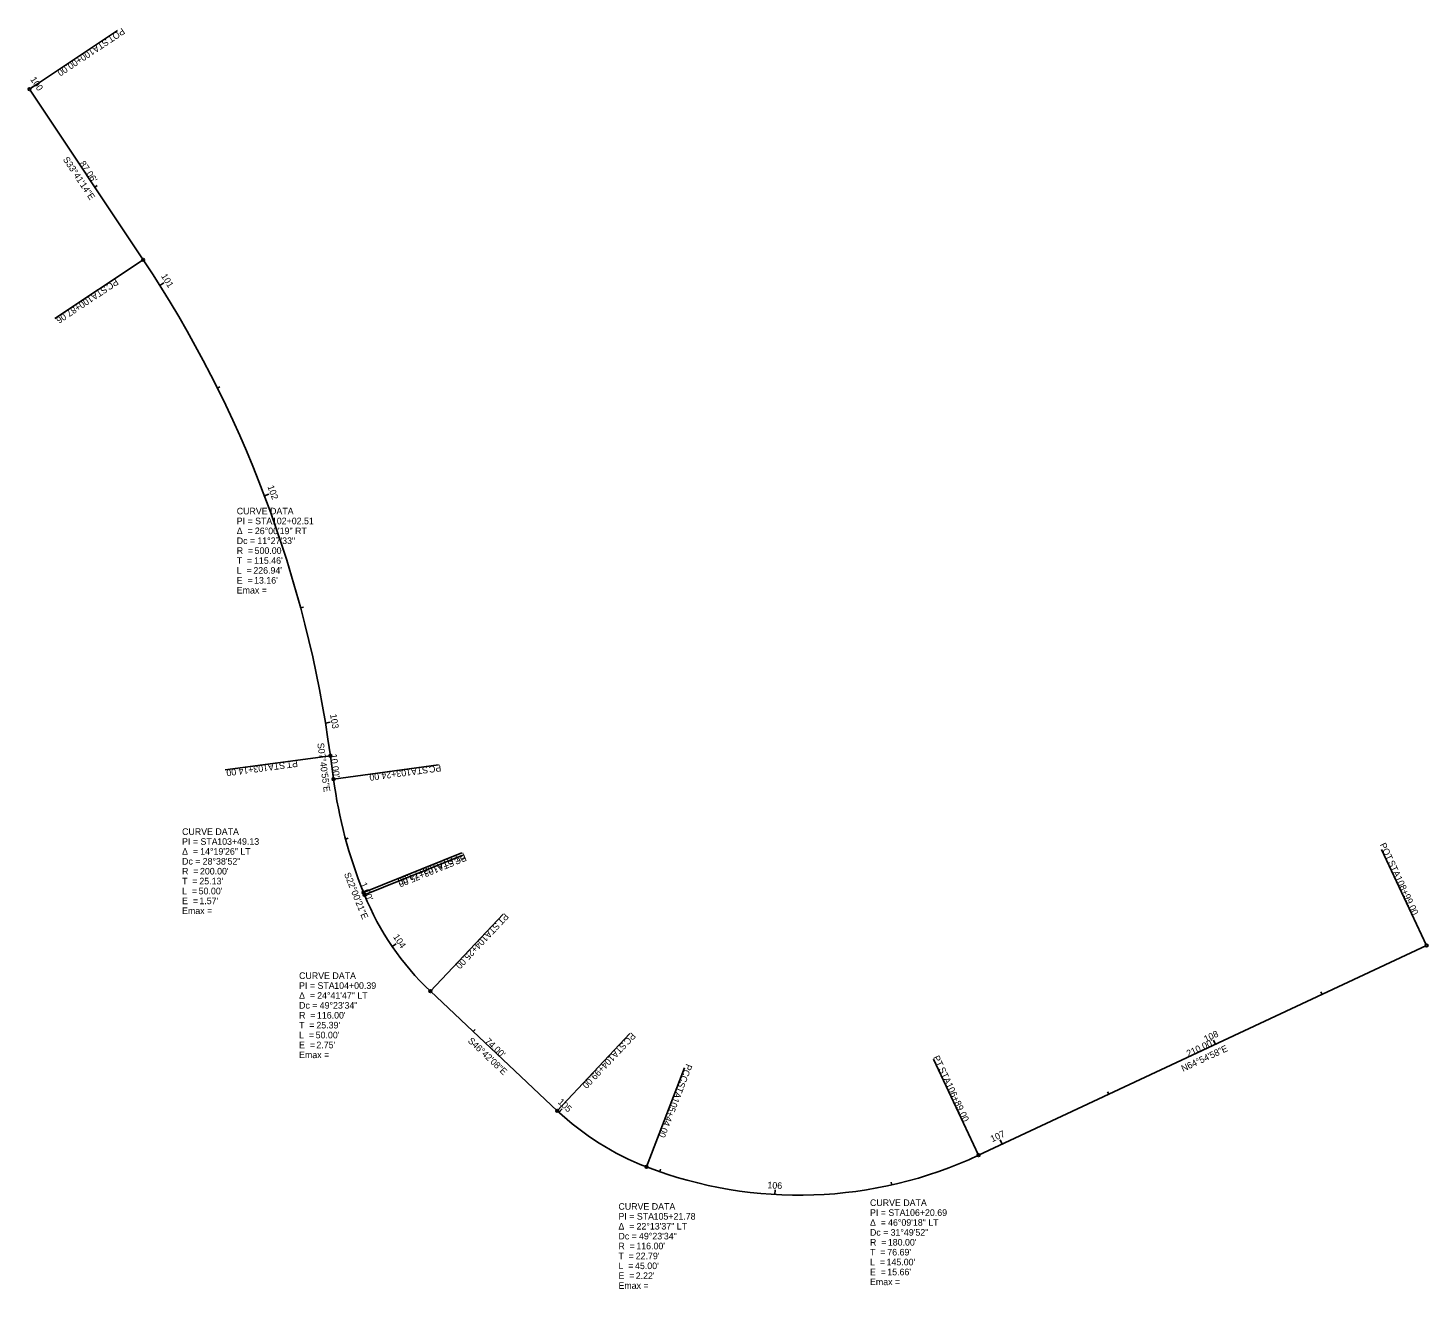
# Model space of a CAD drawing. Extents: x 1865318 to 1865913, y 743981 to 744516.
import ezdxf

# ---------------------------------------------------------------- set-up
doc = ezdxf.new("R2010")
doc.units = 0
for name, color, linetype in [('_CIVIL_CONSTRUCTION', 7, 'Continuous'), ('Default', 7, 'Continuous'), ('GT_Project_Soil_Boring', 7, 'Continuous'), ('PF_P_Text_Curve', 7, 'Continuous'), ('SH_Major_Grid_Line', 7, 'Continuous'), ('SH_Masking', 7, 'Continuous'), ('SH_Text', 7, 'Continuous')]:
    doc.layers.add(name, color=color, linetype=linetype)

msp = doc.modelspace()

# ---------------------------------------------------------------- linework, layer by layer
at = {"layer": 'Default'}
msp.add_line((1865721.96, 744037.44), (1865912.16, 744126.46), dxfattribs=at)
at = {"layer": 'GT_Project_Soil_Boring'}
for p, q in [((1865367.27, 744417.56), (1865318.99, 744490)), ((1865318.99, 744490), (1865367.27, 744417.56)), ((1865318.99, 744490), (1865367.27, 744417.56)), ((1865448.08, 744197.15), (1865446.75, 744207.06)), ((1865446.75, 744207.06), (1865448.08, 744197.15)), ((1865446.75, 744207.06), (1865448.08, 744197.15)), ((1865461.24, 744148.02), (1865460.86, 744148.95)), ((1865460.86, 744148.95), (1865461.24, 744148.02)), ((1865460.86, 744148.95), (1865461.24, 744148.02)), ((1865721.96, 744037.44), (1865912.16, 744126.46)), ((1865489.23, 744107.06), (1865543.09, 744056.31)), ((1865489.23, 744107.06), (1865543.09, 744056.31))]:
    msp.add_line(p, q, dxfattribs=at)
for centre, radius, start, end in [((1864951.23, 744140.23), 500, 7.68182, 33.68723), ((1864951.23, 744140.23), 500, 7.68182, 33.68723), ((1864951.23, 744140.23), 500, 7.68182, 33.68723), ((1865646.29, 744223.89), 200, 187.68182, 202.00577), ((1865646.29, 744223.89), 200, 187.68182, 202.00577), ((1865646.29, 744223.89), 200, 187.68182, 202.00577), ((1865568.78, 744191.49), 116, 202.00577, 226.70222), ((1865568.78, 744191.49), 116, 202.00577, 226.70222), ((1865568.78, 744191.49), 116, 202.00577, 226.70222), ((1865622.64, 744140.74), 116, 226.70222, 248.92903), ((1865622.64, 744140.74), 116, 226.70222, 248.92903), ((1865622.64, 744140.74), 116, 226.70222, 248.92903), ((1865645.65, 744200.46), 180, 248.92903, 295.08397), ((1865645.65, 744200.46), 180, 248.92903, 295.08397), ((1865645.65, 744200.46), 180, 248.92903, 295.08397)]:
    msp.add_arc(centre, radius, start, end, dxfattribs=at)
at = {"layer": 'SH_Major_Grid_Line'}
for p, q in [((1865318.99, 744490), (1865320.65, 744491.11)), ((1865346.72, 744448.39), (1865347.72, 744449.06)), ((1865374.31, 744406.7), (1865376.01, 744407.76)), ((1865398.8, 744363.13), (1865399.88, 744363.66)), ((1865418.82, 744317.33), (1865420.69, 744318.04)), ((1865434.16, 744269.77), (1865435.32, 744270.08)), ((1865444.68, 744220.91), (1865446.66, 744221.23)), ((1865453.22, 744171.68), (1865454.38, 744172)), ((1865473.02, 744126.02), (1865474.67, 744127.15)), ((1865867.78, 744105.69), (1865867.27, 744106.78)), ((1865507.43, 744089.91), (1865508.25, 744090.79)), ((1865822.5, 744084.5), (1865821.65, 744086.31)), ((1865777.21, 744063.3), (1865776.7, 744064.38)), ((1865543.82, 744055.63), (1865545.18, 744057.1)), ((1865731.93, 744042.1), (1865731.08, 744043.91)), ((1865586.57, 744030.43), (1865586.97, 744031.56)), ((1865685.13, 744024.84), (1865684.87, 744026.01)), ((1865635.46, 744020.75), (1865635.58, 744022.74))]:
    msp.add_line(p, q, dxfattribs=at)
at = {"layer": 'SH_Text'}
for p, q in [((1865318.99, 744490), (1865356.43, 744514.96)), ((1865367.27, 744417.56), (1865329.83, 744392.6)), ((1865446.75, 744207.06), (1865402.15, 744201.05)), ((1865448.08, 744197.15), (1865492.68, 744203.17)), ((1865912.16, 744126.46), (1865893.08, 744167.22)), ((1865460.86, 744148.95), (1865502.58, 744165.81)), ((1865461.24, 744148.02), (1865502.96, 744164.88)), ((1865489.23, 744107.06), (1865520.09, 744139.81)), ((1865543.09, 744056.31), (1865573.95, 744089.06)), ((1865721.96, 744037.44), (1865702.88, 744078.19)), ((1865580.94, 744032.49), (1865597.11, 744074.49))]:
    msp.add_line(p, q, dxfattribs=at)
for centre in [(1865318.99, 744490), (1865367.27, 744417.56), (1865446.75, 744207.06), (1865448.08, 744197.15), (1865460.86, 744148.95), (1865461.24, 744148.02), (1865912.16, 744126.46), (1865489.23, 744107.06), (1865543.09, 744056.31), (1865721.96, 744037.44), (1865580.94, 744032.49)]:
    msp.add_circle(centre, 0.6, dxfattribs=at)

# ---------------------------------------------------------------- texts
at = {"layer": '_CIVIL_CONSTRUCTION'}
for s, rotation, p in [("87.06'", 303.68723, (1865340.08, 744458.43)), ("10.00'", 277.68182, (1865446.71, 744207.63)), ("1.00'", 292.00577, (1865459.42, 744152.62)), ("74.00'", 316.70222, (1865512.14, 744085.53)), ("210.00'", 25.08397, (1865810.99, 744079.16))]:
    msp.add_text(s, height=2.8, rotation=rotation, dxfattribs=at).set_placement(p)
at = {"layer": 'PF_P_Text_Curve'}
for s, p in [('CURVE DATA', (1865407.01, 744309.51)), ('Δ  = ', (1865407.01, 744301.11)), ('PI = STA ', (1865407.01, 744305.31)), ('26°00\'19" RT', (1865414.69, 744301.11)), ('102+02.51', (1865421.93, 744305.31)), ('Dc = ', (1865407.01, 744296.91)), ('11°27\'33"', (1865415.75, 744296.91)), ('R  = ', (1865407.01, 744292.71)), ("115.46'", (1865414.35, 744288.51)), ("500.00'", (1865414.59, 744292.71)), ('T  = ', (1865407.01, 744288.51)), ('L  = ', (1865407.01, 744284.31)), ("226.94'", (1865414.05, 744284.31)), ('E  = ', (1865407.01, 744280.11)), ("13.16'", (1865414.35, 744280.11)), ('Emax = ', (1865407.01, 744275.91)), ('CURVE DATA', (1865383.8, 744173.42)), ('Δ  = ', (1865383.8, 744165.02)), ('PI = STA ', (1865383.8, 744169.22)), ('14°19\'26" LT', (1865391.48, 744165.02)), ('103+49.13', (1865398.73, 744169.22)), ('Dc = ', (1865383.8, 744160.82)), ('28°38\'52"', (1865392.54, 744160.82)), ('T  = ', (1865383.8, 744152.42)), ('R  = ', (1865383.8, 744156.62)), ("25.13'", (1865391.14, 744152.42)), ("200.00'", (1865391.39, 744156.62)), ('L  = ', (1865383.8, 744148.22)), ("50.00'", (1865390.85, 744148.22)), ('E  = ', (1865383.8, 744144.02)), ("1.57'", (1865391.15, 744144.02)), ('Emax = ', (1865383.8, 744139.82)), ('CURVE DATA', (1865433.48, 744112.26)), ('PI = STA ', (1865433.48, 744108.06)), ('104+00.39', (1865448.4, 744108.06)), ('Δ  = ', (1865433.48, 744103.86)), ('Dc = ', (1865433.48, 744099.66)), ('24°41\'47" LT', (1865441.15, 744103.86)), ('49°23\'34"', (1865442.22, 744099.66)), ('R  = ', (1865433.48, 744095.46)), ("116.00'", (1865441.06, 744095.46)), ('T  = ', (1865433.48, 744091.26)), ('L  = ', (1865433.48, 744087.06)), ("50.00'", (1865440.52, 744087.06)), ("25.39'", (1865440.82, 744091.26)), ('E  = ', (1865433.48, 744082.86)), ("2.75'", (1865440.82, 744082.86)), ('Emax = ', (1865433.48, 744078.66)), ('CURVE DATA', (1865675.85, 744015.88)), ('CURVE DATA', (1865569.06, 744014.29)), ('PI = STA ', (1865569.06, 744010.09)), ('105+21.78', (1865583.99, 744010.09)), ('PI = STA ', (1865675.85, 744011.68)), ('106+20.69', (1865690.77, 744011.68)), ('Δ  = ', (1865569.06, 744005.89)), ('22°13\'37" LT', (1865576.74, 744005.89)), ('Δ  = ', (1865675.85, 744007.48)), ('Dc = ', (1865675.85, 744003.28)), ('46°09\'18" LT', (1865683.53, 744007.48)), ('31°49\'52"', (1865684.59, 744003.28)), ('Dc = ', (1865569.06, 744001.69)), ('R  = ', (1865569.06, 743997.49)), ("116.00'", (1865576.65, 743997.49)), ('49°23\'34"', (1865577.8, 744001.69)), ('R  = ', (1865675.85, 743999.08)), ("180.00'", (1865683.43, 743999.08)), ('T  = ', (1865569.06, 743993.29)), ("22.79'", (1865576.4, 743993.29)), ('T  = ', (1865675.85, 743994.88)), ("76.69'", (1865683.19, 743994.88)), ('L  = ', (1865569.06, 743989.09)), ("45.00'", (1865576.1, 743989.09)), ('L  = ', (1865675.85, 743990.68)), ('E  = ', (1865675.85, 743986.48)), ("145.00'", (1865682.89, 743990.68)), ("15.66'", (1865683.19, 743986.48)), ('E  = ', (1865569.06, 743984.89)), ('Emax = ', (1865569.06, 743980.69)), ("2.22'", (1865576.4, 743984.89)), ('Emax = ', (1865675.85, 743982.28))]:
    msp.add_text(s, height=2.8, dxfattribs=at).set_placement(p)
at = {"layer": 'SH_Major_Grid_Line'}
for s, rotation, p in [('100', 303.68723, (1865319.21, 744494.17)), ('101', 302.20396, (1865374.75, 744410.69)), ('102', 290.7448, (1865419.99, 744321.28)), ('103', 279.28564, (1865446.62, 744224.54)), ('104', 304.35597, (1865473.24, 744130.14)), ('108', 25.08397, (1865818.42, 744085.35)), ('105', 317.19813, (1865543.1, 744059.71)), ('107', 25.08397, (1865727.77, 744042.92)), ('106', 356.75566, (1865632.25, 744023.43))]:
    msp.add_text(s, height=2.8, rotation=rotation, dxfattribs=at).set_placement(p)
at = {"layer": 'SH_Masking'}
for s, rotation, p in [('S33°41\'14"E', 303.68723, (1865333.07, 744460.22)), ('S07°40\'55"E', 277.68182, (1865441.2, 744212.31)), ('S22°00\'21"E', 292.00577, (1865452.5, 744156.83)), ('S46°42\'08"E', 316.70222, (1865504.91, 744085.7)), ('N64°54\'58"E', 25.08397, (1865808.8, 744072.79))]:
    msp.add_text(s, height=2.8, rotation=rotation, dxfattribs=at).set_placement(p)
at = {"layer": 'SH_Text'}
for s, rotation, p in [(' STA ', 213.68723, (1865352.33, 744512.17)), ('POT', 213.68723, (1865358.32, 744516.16)), ('100+00.00', 213.68723, (1865345.39, 744507.55)), (' STA ', 213.68723, (1865351.79, 744407.18)), ('PC', 213.68723, (1865355.6, 744409.73)), ('100+87.06', 213.68723, (1865344.85, 744402.56)), ('103+14.00', 187.68182, (1865420.09, 744203.43)), (' STA ', 187.68182, (1865428.35, 744204.54)), ('PT', 187.68182, (1865432.73, 744205.13)), (' STA ', 187.68182, (1865489.07, 744202.64)), ('PC', 187.68182, (1865493.61, 744203.25)), ('103+24.00', 187.68182, (1865480.81, 744201.53)), ('POT', 295.08397, (1865892.17, 744169.27)), ('103+74.00', 202.00577, (1865491.56, 744161.31)), (' STA ', 202.00577, (1865499.29, 744164.44)), (' STA ', 202.00577, (1865499.59, 744163.48)), ('PC', 202.00577, (1865503.84, 744165.19)), ('PT', 202.00577, (1865503.38, 744166.09)), (' STA ', 295.08397, (1865895.22, 744162.75)), ('103+75.00', 202.00577, (1865491.86, 744160.35)), ('108+99.00', 295.08397, (1865898.75, 744155.2)), ('PT', 226.70222, (1865520.71, 744140.4)), ('104+25.00', 226.70222, (1865511.96, 744131.12)), (' STA ', 226.70222, (1865517.68, 744137.19)), ('PC', 226.70222, (1865574.62, 744089.72)), (' STA ', 226.70222, (1865571.48, 744086.38)), ('104+99.00', 226.70222, (1865565.76, 744080.31)), ('PT', 295.08397, (1865702.56, 744078.98)), ('PCC', 248.92903, (1865597.9, 744076.42)), (' STA ', 295.08397, (1865704.43, 744074.98)), (' STA ', 248.92903, (1865595.43, 744069.99)), ('106+89.00', 295.08397, (1865707.97, 744067.43)), ('105+44.00', 248.92903, (1865592.43, 744062.21))]:
    msp.add_text(s, height=2.8, rotation=rotation, dxfattribs=at).set_placement(p)

doc.saveas('drawing.dxf')
